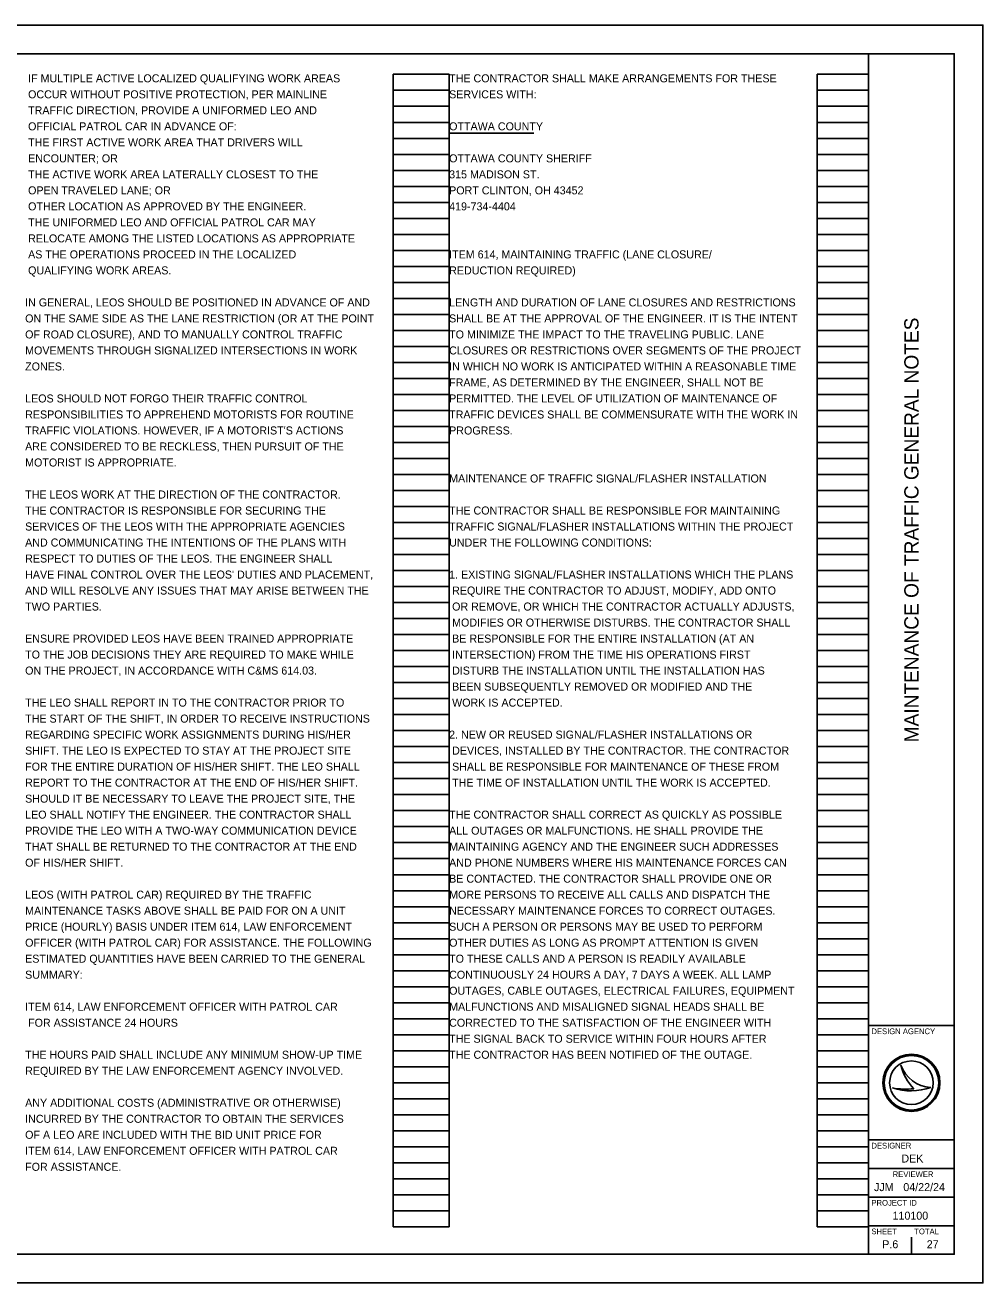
# Model space of a CAD drawing. Extents: x 0 to 34, y 0 to 22.
# Drawn here: x 17.24 to 34, y 0 to 22 of the extents above; entities that cross this region are included whole.
import ezdxf

# ---------------------------------------------------------------- set-up
doc = ezdxf.new("R2010")
doc.units = 0
for name, color, linetype in [('SH_Border', 7, 'Continuous'), ('SH_Cut_Line', 7, 'Continuous'), ('SH_Data', 7, 'Continuous'), ('SH_Text', 7, 'Continuous')]:
    doc.layers.add(name, color=color, linetype=linetype)

msp = doc.modelspace()

# ---------------------------------------------------------------- linework, layer by layer
at = {"layer": 'SH_Border'}
for p, q in [((32, 0.5), (32, 21.5)), ((32, 4.5), (33.5, 4.5)), ((32, 2.5), (33.5, 2.5)), ((32, 2), (33.5, 2)), ((32, 1.5), (33.5, 1.5)), ((32, 1), (33.5, 1))]:
    msp.add_line(p, q, dxfattribs=at)
msp.add_lwpolyline([(1.5, 21.5), (33.5, 21.5), (33.5, 0.5), (1.5, 0.5)], close=True, dxfattribs=at)
at = {"layer": 'SH_Cut_Line'}
msp.add_lwpolyline([(0, 0), (34, 0), (34, 22), (0, 22)], close=True, dxfattribs=at)
at = {"layer": 'SH_Data'}
for p, q in [((23.68, 0.98), (23.68, 21.14)), ((23.68, 21.14), (24.66, 21.14)), ((24.66, 0.98), (24.66, 21.14)), ((31.1, 0.98), (31.1, 21.14)), ((31.1, 21.14), (32, 21.14)), ((32, 0.98), (32, 21.14)), ((23.68, 20.86), (24.66, 20.86)), ((31.1, 20.86), (32, 20.86)), ((23.68, 20.58), (24.66, 20.58)), ((31.1, 20.58), (32, 20.58)), ((23.68, 20.3), (24.66, 20.3)), ((31.1, 20.3), (32, 20.3)), ((23.68, 20.02), (24.66, 20.02)), ((31.1, 20.02), (32, 20.02)), ((23.68, 19.74), (24.66, 19.74)), ((31.1, 19.74), (32, 19.74)), ((23.68, 19.46), (24.66, 19.46)), ((31.1, 19.46), (32, 19.46)), ((23.68, 19.18), (24.66, 19.18)), ((31.1, 19.18), (32, 19.18)), ((23.68, 18.9), (24.66, 18.9)), ((31.1, 18.9), (32, 18.9)), ((23.68, 18.62), (24.66, 18.62)), ((31.1, 18.62), (32, 18.62)), ((23.68, 18.34), (24.66, 18.34)), ((31.1, 18.34), (32, 18.34)), ((23.68, 18.06), (24.66, 18.06)), ((31.1, 18.06), (32, 18.06)), ((23.68, 17.78), (24.66, 17.78)), ((31.1, 17.78), (32, 17.78)), ((23.68, 17.5), (24.66, 17.5)), ((31.1, 17.5), (32, 17.5)), ((23.68, 17.22), (24.66, 17.22)), ((31.1, 17.22), (32, 17.22)), ((23.68, 16.94), (24.66, 16.94)), ((31.1, 16.94), (32, 16.94)), ((23.68, 16.66), (24.66, 16.66)), ((31.1, 16.66), (32, 16.66)), ((23.68, 16.38), (24.66, 16.38)), ((31.1, 16.38), (32, 16.38)), ((23.68, 16.1), (24.66, 16.1)), ((31.1, 16.1), (32, 16.1)), ((23.68, 15.82), (24.66, 15.82)), ((31.1, 15.82), (32, 15.82)), ((23.68, 15.54), (24.66, 15.54)), ((31.1, 15.54), (32, 15.54)), ((23.68, 15.26), (24.66, 15.26)), ((31.1, 15.26), (32, 15.26)), ((23.68, 14.98), (24.66, 14.98)), ((31.1, 14.98), (32, 14.98)), ((23.68, 14.7), (24.66, 14.7)), ((31.1, 14.7), (32, 14.7)), ((23.68, 14.42), (24.66, 14.42)), ((31.1, 14.42), (32, 14.42)), ((23.68, 14.14), (24.66, 14.14)), ((31.1, 14.14), (32, 14.14)), ((23.68, 13.86), (24.66, 13.86)), ((31.1, 13.86), (32, 13.86)), ((23.68, 13.58), (24.66, 13.58)), ((31.1, 13.58), (32, 13.58)), ((23.68, 13.3), (24.66, 13.3)), ((31.1, 13.3), (32, 13.3)), ((23.68, 13.02), (24.66, 13.02)), ((31.1, 13.02), (32, 13.02)), ((23.68, 12.74), (24.66, 12.74)), ((31.1, 12.74), (32, 12.74)), ((23.68, 12.46), (24.66, 12.46)), ((31.1, 12.46), (32, 12.46)), ((23.68, 12.18), (24.66, 12.18)), ((31.1, 12.18), (32, 12.18)), ((23.68, 11.9), (24.66, 11.9)), ((31.1, 11.9), (32, 11.9)), ((23.68, 11.62), (24.66, 11.62)), ((31.1, 11.62), (32, 11.62)), ((23.68, 11.34), (24.66, 11.34)), ((31.1, 11.34), (32, 11.34)), ((23.68, 11.06), (24.66, 11.06)), ((31.1, 11.06), (32, 11.06)), ((23.68, 10.78), (24.66, 10.78)), ((31.1, 10.78), (32, 10.78)), ((23.68, 10.5), (24.66, 10.5)), ((31.1, 10.5), (32, 10.5)), ((23.68, 10.22), (24.66, 10.22)), ((31.1, 10.22), (32, 10.22)), ((23.68, 9.94), (24.66, 9.94)), ((31.1, 9.94), (32, 9.94)), ((23.68, 9.66), (24.66, 9.66)), ((31.1, 9.66), (32, 9.66)), ((23.68, 9.38), (24.66, 9.38)), ((31.1, 9.38), (32, 9.38)), ((23.68, 9.1), (24.66, 9.1)), ((31.1, 9.1), (32, 9.1)), ((23.68, 8.82), (24.66, 8.82)), ((31.1, 8.82), (32, 8.82)), ((23.68, 8.54), (24.66, 8.54)), ((31.1, 8.54), (32, 8.54)), ((23.68, 8.26), (24.66, 8.26)), ((31.1, 8.26), (32, 8.26)), ((23.68, 7.98), (24.66, 7.98)), ((31.1, 7.98), (32, 7.98)), ((23.68, 7.7), (24.66, 7.7)), ((31.1, 7.7), (32, 7.7)), ((23.68, 7.42), (24.66, 7.42)), ((31.1, 7.42), (32, 7.42)), ((23.68, 7.14), (24.66, 7.14)), ((31.1, 7.14), (32, 7.14)), ((23.68, 6.86), (24.66, 6.86)), ((31.1, 6.86), (32, 6.86)), ((23.68, 6.58), (24.66, 6.58)), ((31.1, 6.58), (32, 6.58)), ((23.68, 6.3), (24.66, 6.3)), ((31.1, 6.3), (32, 6.3)), ((23.68, 6.02), (24.66, 6.02)), ((31.1, 6.02), (32, 6.02)), ((23.68, 5.74), (24.66, 5.74)), ((31.1, 5.74), (32, 5.74)), ((23.68, 5.46), (24.66, 5.46)), ((31.1, 5.46), (32, 5.46)), ((23.68, 5.18), (24.66, 5.18)), ((31.1, 5.18), (32, 5.18)), ((23.68, 4.9), (24.66, 4.9)), ((31.1, 4.9), (32, 4.9)), ((23.68, 4.62), (24.66, 4.62)), ((31.1, 4.62), (32, 4.62)), ((23.68, 4.34), (24.66, 4.34)), ((31.1, 4.34), (32, 4.34)), ((23.68, 4.06), (24.66, 4.06)), ((31.1, 4.06), (32, 4.06)), ((23.68, 3.78), (24.66, 3.78)), ((31.1, 3.78), (32, 3.78)), ((32.567, 3.81), (32.567, 3.81)), ((23.68, 3.5), (24.66, 3.5)), ((31.1, 3.5), (32, 3.5)), ((32.417, 3.41), (32.417, 3.41)), ((32.75, 3.5), (32.75, 3.5)), ((33.087, 3.419), (33.087, 3.419)), ((23.68, 3.22), (24.66, 3.22)), ((31.1, 3.22), (32, 3.22)), ((23.68, 2.94), (24.66, 2.94)), ((31.1, 2.94), (32, 2.94)), ((23.68, 2.66), (24.66, 2.66)), ((31.1, 2.66), (32, 2.66)), ((23.68, 2.38), (24.66, 2.38)), ((31.1, 2.38), (32, 2.38)), ((23.68, 2.1), (24.66, 2.1)), ((31.1, 2.1), (32, 2.1)), ((23.68, 1.82), (24.66, 1.82)), ((31.1, 1.82), (32, 1.82)), ((23.68, 1.54), (24.66, 1.54)), ((31.1, 1.54), (32, 1.54)), ((23.68, 1.26), (24.66, 1.26)), ((31.1, 1.26), (32, 1.26)), ((23.68, 0.98), (24.66, 0.98)), ((31.1, 0.98), (32, 0.98)), ((32.375, 0.675), (32.375, 0.675)), ((32.75, 0.5), (32.75, 0.8))]:
    msp.add_line(p, q, dxfattribs=at)
for radius in [0.5, 0.477, 0.477, 0.382]:
    msp.add_circle((32.75, 3.5), radius, dxfattribs=at)
for centre, radius, start, end in [((33.116, 3.998), 0.58, 198.9257, 198.9319), ((33.347, 3.97), 0.796, 191.6379, 191.6421), ((33.116, 3.998), 0.58, 198.9319, 267.1657), ((33.347, 3.97), 0.796, 191.6421, 226.0947), ((32.739, 4.37), 1.013, 251.4576, 290.0832), ((32.648, 4.654), 1.266, 259.4964, 259.4995), ((32.739, 4.37), 1.013, 251.4527, 251.4576), ((32.648, 4.654), 1.266, 259.4995, 276.6672)]:
    msp.add_arc(centre, radius, start, end, dxfattribs=at)
at = {"layer": 'SH_Text'}
msp.add_line((24.646, 20.111), (26.141, 20.111), dxfattribs=at)

# ---------------------------------------------------------------- texts
at = {"layer": 'SH_Data'}
msp.add_text('MAINTENANCE OF TRAFFIC GENERAL NOTES', height=0.25, rotation=90, dxfattribs=at).set_placement((32.875, 9.455))
for s, height, p in [('DESIGN AGENCY', 0.1, (32.05, 4.35)), ('DESIGNER', 0.1, (32.05, 2.35)), ('DEK', 0.14, (32.574, 2.105)), ('REVIEWER', 0.1, (32.422, 1.85)), ('JJM', 0.14, (32.095, 1.605)), ('04/22/24', 0.14, (32.608, 1.605)), ('PROJECT ID', 0.1, (32.05, 1.35)), ('110100', 0.14, (32.419, 1.105)), ('SHEET', 0.1, (32.05, 0.85)), ('TOTAL', 0.1, (32.8, 0.85)), ('P.6', 0.14, (32.239, 0.605)), ('27', 0.14, (33.018, 0.605))]:
    msp.add_text(s, height=height, dxfattribs=at).set_placement(p)
at = {"layer": 'SH_Text'}
for s, p in [(' IF MULTIPLE ACTIVE LOCALIZED QUALIFYING WORK AREAS', (17.24, 21)), ('THE CONTRACTOR SHALL MAKE ARRANGEMENTS FOR THESE', (24.66, 21)), (' OCCUR WITHOUT POSITIVE PROTECTION, PER MAINLINE', (17.24, 20.72)), ('SERVICES WITH:', (24.66, 20.72)), (' TRAFFIC DIRECTION, PROVIDE A UNIFORMED LEO AND', (17.24, 20.44)), (' OFFICIAL PATROL CAR IN ADVANCE OF:', (17.24, 20.16)), ('OTTAWA COUNTY', (24.66, 20.16)), (' THE FIRST ACTIVE WORK AREA THAT DRIVERS WILL', (17.24, 19.88)), (' ENCOUNTER; OR', (17.24, 19.6)), ('OTTAWA COUNTY SHERIFF', (24.66, 19.6)), (' THE ACTIVE WORK AREA LATERALLY CLOSEST TO THE', (17.24, 19.32)), ('315 MADISON ST.', (24.66, 19.32)), (' OPEN TRAVELED LANE; OR', (17.24, 19.04)), ('PORT CLINTON, OH 43452', (24.66, 19.04)), (' OTHER LOCATION AS APPROVED BY THE ENGINEER.', (17.24, 18.76)), ('419-734-4404', (24.66, 18.76)), (' THE UNIFORMED LEO AND OFFICIAL PATROL CAR MAY', (17.24, 18.48)), (' RELOCATE AMONG THE LISTED LOCATIONS AS APPROPRIATE', (17.24, 18.2)), (' AS THE OPERATIONS PROCEED IN THE LOCALIZED', (17.24, 17.92)), ('ITEM 614, MAINTAINING TRAFFIC (LANE CLOSURE/', (24.66, 17.92)), (' QUALIFYING WORK AREAS.', (17.24, 17.64)), ('REDUCTION REQUIRED)', (24.66, 17.64)), ('IN GENERAL, LEOS SHOULD BE POSITIONED IN ADVANCE OF AND', (17.24, 17.08)), ('LENGTH AND DURATION OF LANE CLOSURES AND RESTRICTIONS', (24.66, 17.08)), ('ON THE SAME SIDE AS THE LANE RESTRICTION (OR AT THE POINT', (17.24, 16.8)), ('SHALL BE AT THE APPROVAL OF THE ENGINEER. IT IS THE INTENT', (24.66, 16.8)), ('OF ROAD CLOSURE), AND TO MANUALLY CONTROL TRAFFIC', (17.24, 16.52)), ('TO MINIMIZE THE IMPACT TO THE TRAVELING PUBLIC. LANE', (24.66, 16.52)), ('MOVEMENTS THROUGH SIGNALIZED INTERSECTIONS IN WORK', (17.24, 16.24)), ('CLOSURES OR RESTRICTIONS OVER SEGMENTS OF THE PROJECT', (24.66, 16.24)), ('ZONES.', (17.24, 15.96)), ('IN WHICH NO WORK IS ANTICIPATED WITHIN A REASONABLE TIME', (24.66, 15.96)), ('FRAME, AS DETERMINED BY THE ENGINEER, SHALL NOT BE', (24.66, 15.68)), ('LEOS SHOULD NOT FORGO THEIR TRAFFIC CONTROL', (17.24, 15.4)), ('PERMITTED. THE LEVEL OF UTILIZATION OF MAINTENANCE OF', (24.66, 15.4)), ('RESPONSIBILITIES TO APPREHEND MOTORISTS FOR ROUTINE', (17.24, 15.12)), ('TRAFFIC DEVICES SHALL BE COMMENSURATE WITH THE WORK IN', (24.66, 15.12)), ("TRAFFIC VIOLATIONS. HOWEVER, IF A MOTORIST'S ACTIONS", (17.24, 14.84)), ('PROGRESS.', (24.66, 14.84)), ('ARE CONSIDERED TO BE RECKLESS, THEN PURSUIT OF THE', (17.24, 14.56)), ('MOTORIST IS APPROPRIATE.', (17.24, 14.28)), ('MAINTENANCE OF TRAFFIC SIGNAL/FLASHER INSTALLATION', (24.66, 14)), ('THE LEOS WORK AT THE DIRECTION OF THE CONTRACTOR.', (17.24, 13.72)), ('THE CONTRACTOR IS RESPONSIBLE FOR SECURING THE', (17.24, 13.44)), ('THE CONTRACTOR SHALL BE RESPONSIBLE FOR MAINTAINING', (24.66, 13.44)), ('SERVICES OF THE LEOS WITH THE APPROPRIATE AGENCIES', (17.24, 13.16)), ('TRAFFIC SIGNAL/FLASHER INSTALLATIONS WITHIN THE PROJECT', (24.66, 13.16)), ('AND COMMUNICATING THE INTENTIONS OF THE PLANS WITH', (17.24, 12.88)), ('UNDER THE FOLLOWING CONDITIONS:', (24.66, 12.88)), ('RESPECT TO DUTIES OF THE LEOS. THE ENGINEER SHALL', (17.24, 12.6)), ("HAVE FINAL CONTROL OVER THE LEOS' DUTIES AND PLACEMENT,", (17.24, 12.32)), ('1. EXISTING SIGNAL/FLASHER INSTALLATIONS WHICH THE PLANS', (24.66, 12.32)), ('AND WILL RESOLVE ANY ISSUES THAT MAY ARISE BETWEEN THE', (17.24, 12.04)), (' REQUIRE THE CONTRACTOR TO ADJUST, MODIFY, ADD ONTO', (24.66, 12.04)), ('TWO PARTIES.', (17.24, 11.76)), (' OR REMOVE, OR WHICH THE CONTRACTOR ACTUALLY ADJUSTS,', (24.66, 11.76)), (' MODIFIES OR OTHERWISE DISTURBS. THE CONTRACTOR SHALL', (24.66, 11.48)), ('ENSURE PROVIDED LEOS HAVE BEEN TRAINED APPROPRIATE', (17.24, 11.2)), (' BE RESPONSIBLE FOR THE ENTIRE INSTALLATION (AT AN', (24.66, 11.2)), ('TO THE JOB DECISIONS THEY ARE REQUIRED TO MAKE WHILE', (17.24, 10.92)), (' INTERSECTION) FROM THE TIME HIS OPERATIONS FIRST', (24.66, 10.92)), ('ON THE PROJECT, IN ACCORDANCE WITH C&MS 614.03.', (17.24, 10.64)), (' DISTURB THE INSTALLATION UNTIL THE INSTALLATION HAS', (24.66, 10.64)), (' BEEN SUBSEQUENTLY REMOVED OR MODIFIED AND THE', (24.66, 10.36)), ('THE LEO SHALL REPORT IN TO THE CONTRACTOR PRIOR TO', (17.24, 10.08)), (' WORK IS ACCEPTED.', (24.66, 10.08)), ('THE START OF THE SHIFT, IN ORDER TO RECEIVE INSTRUCTIONS', (17.24, 9.8)), ('REGARDING SPECIFIC WORK ASSIGNMENTS DURING HIS/HER', (17.24, 9.52)), ('2. NEW OR REUSED SIGNAL/FLASHER INSTALLATIONS OR', (24.66, 9.52)), ('SHIFT. THE LEO IS EXPECTED TO STAY AT THE PROJECT SITE', (17.24, 9.24)), (' DEVICES, INSTALLED BY THE CONTRACTOR. THE CONTRACTOR', (24.66, 9.24)), ('FOR THE ENTIRE DURATION OF HIS/HER SHIFT. THE LEO SHALL', (17.24, 8.96)), (' SHALL BE RESPONSIBLE FOR MAINTENANCE OF THESE FROM', (24.66, 8.96)), ('REPORT TO THE CONTRACTOR AT THE END OF HIS/HER SHIFT.', (17.24, 8.68)), (' THE TIME OF INSTALLATION UNTIL THE WORK IS ACCEPTED.', (24.66, 8.68)), ('SHOULD IT BE NECESSARY TO LEAVE THE PROJECT SITE, THE', (17.24, 8.4)), ('LEO SHALL NOTIFY THE ENGINEER. THE CONTRACTOR SHALL', (17.24, 8.12)), ('THE CONTRACTOR SHALL CORRECT AS QUICKLY AS POSSIBLE', (24.66, 8.12)), ('PROVIDE THE LEO WITH A TWO-WAY COMMUNICATION DEVICE', (17.24, 7.84)), ('ALL OUTAGES OR MALFUNCTIONS. HE SHALL PROVIDE THE', (24.66, 7.84)), ('THAT SHALL BE RETURNED TO THE CONTRACTOR AT THE END', (17.24, 7.56)), ('MAINTAINING AGENCY AND THE ENGINEER SUCH ADDRESSES', (24.66, 7.56)), ('OF HIS/HER SHIFT.', (17.24, 7.28)), ('AND PHONE NUMBERS WHERE HIS MAINTENANCE FORCES CAN', (24.66, 7.28)), ('BE CONTACTED. THE CONTRACTOR SHALL PROVIDE ONE OR', (24.66, 7)), ('LEOS (WITH PATROL CAR) REQUIRED BY THE TRAFFIC', (17.24, 6.72)), ('MORE PERSONS TO RECEIVE ALL CALLS AND DISPATCH THE', (24.66, 6.72)), ('MAINTENANCE TASKS ABOVE SHALL BE PAID FOR ON A UNIT', (17.24, 6.44)), ('NECESSARY MAINTENANCE FORCES TO CORRECT OUTAGES.', (24.66, 6.44)), ('PRICE (HOURLY) BASIS UNDER ITEM 614, LAW ENFORCEMENT', (17.24, 6.16)), ('SUCH A PERSON OR PERSONS MAY BE USED TO PERFORM', (24.66, 6.16)), ('OFFICER (WITH PATROL CAR) FOR ASSISTANCE. THE FOLLOWING', (17.24, 5.88)), ('OTHER DUTIES AS LONG AS PROMPT ATTENTION IS GIVEN', (24.66, 5.88)), ('ESTIMATED QUANTITIES HAVE BEEN CARRIED TO THE GENERAL', (17.24, 5.6)), ('TO THESE CALLS AND A PERSON IS READILY AVAILABLE', (24.66, 5.6)), ('SUMMARY:', (17.24, 5.32)), ('CONTINUOUSLY 24 HOURS A DAY, 7 DAYS A WEEK. ALL LAMP', (24.66, 5.32)), ('OUTAGES, CABLE OUTAGES, ELECTRICAL FAILURES, EQUIPMENT', (24.66, 5.04)), ('ITEM 614, LAW ENFORCEMENT OFFICER WITH PATROL CAR', (17.24, 4.76)), ('MALFUNCTIONS AND MISALIGNED SIGNAL HEADS SHALL BE', (24.66, 4.76)), (' FOR ASSISTANCE 24 HOURS', (17.24, 4.48)), ('CORRECTED TO THE SATISFACTION OF THE ENGINEER WITH', (24.66, 4.48)), ('THE SIGNAL BACK TO SERVICE WITHIN FOUR HOURS AFTER', (24.66, 4.2)), ('THE HOURS PAID SHALL INCLUDE ANY MINIMUM SHOW-UP TIME', (17.24, 3.92)), ('THE CONTRACTOR HAS BEEN NOTIFIED OF THE OUTAGE.', (24.66, 3.92)), ('REQUIRED BY THE LAW ENFORCEMENT AGENCY INVOLVED.', (17.24, 3.64)), ('ANY ADDITIONAL COSTS (ADMINISTRATIVE OR OTHERWISE)', (17.24, 3.08)), ('INCURRED BY THE CONTRACTOR TO OBTAIN THE SERVICES', (17.24, 2.8)), ('OF A LEO ARE INCLUDED WITH THE BID UNIT PRICE FOR', (17.24, 2.52)), ('ITEM 614, LAW ENFORCEMENT OFFICER WITH PATROL CAR', (17.24, 2.24)), ('FOR ASSISTANCE.', (17.24, 1.96))]:
    msp.add_text(s, height=0.14, dxfattribs=at).set_placement(p)

doc.saveas('drawing.dxf')
